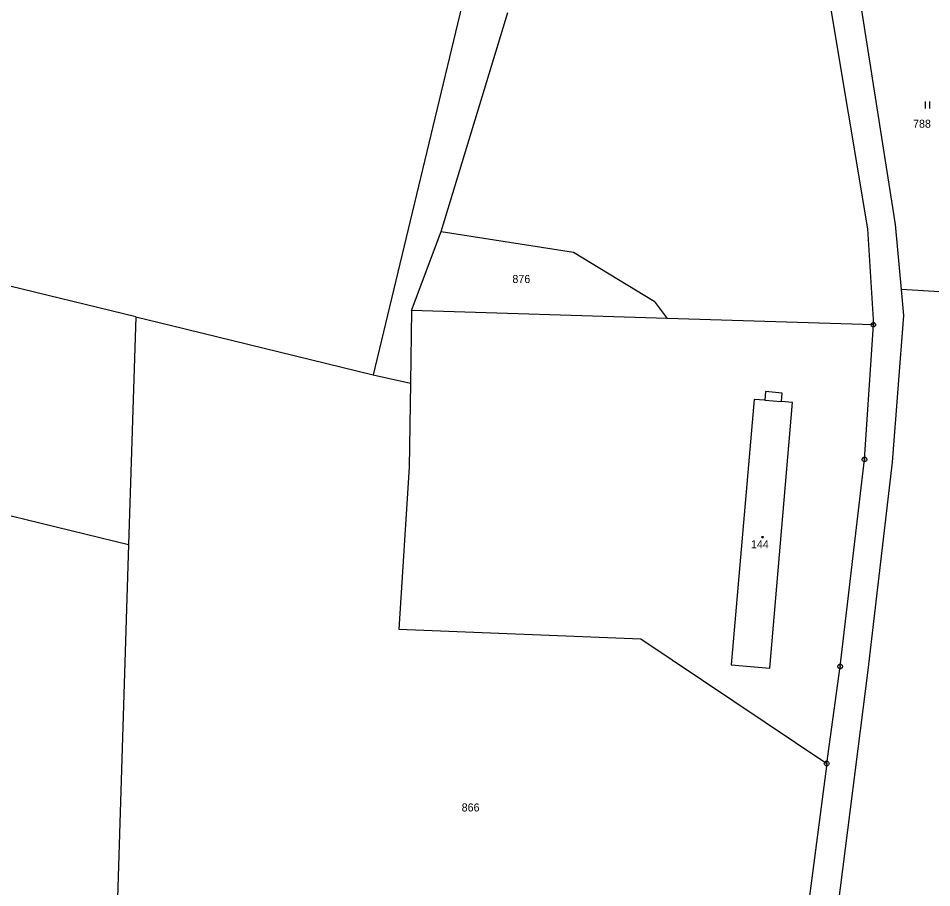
# Model space of a CAD drawing. Extents: x -812394 to -807601, y -1013098 to -1009266.
# Drawn here: x -809612.2 to -809418.3, y -1010586.4 to -1010401.8 of the extents above; entities that cross this region are included whole.
import ezdxf

# ---------------------------------------------------------------- set-up
doc = ezdxf.new("R2010")
doc.units = 0
for name, color, linetype in [('KN_HRANICE', 7, 'Continuous'), ('KN_KULTURY', 7, 'Continuous'), ('KN_MEZNIKY', 7, 'Continuous'), ('KN_PARCELY', 7, 'Continuous'), ('KN_SLUCKY', 7, 'Continuous')]:
    doc.layers.add(name, color=color, linetype=linetype)

# ---------------------------------------------------------------- blocks, each defined once
blk = doc.blocks.new('306')
for p, q in [((-0.5, 1.5), (-0.5, 0)), ((0.5, 0), (0.5, 1.5))]:
    blk.add_line(p, q)
blk = doc.blocks.new('105')
blk.add_line((-0.12, 0), (0.12, 0))
blk.add_lwpolyline([(0.15, 0.48), (0.4, 0.3), (0.5, 0.01), (0.4, -0.28), (0.15, -0.46), (-0.16, -0.46), (-0.41, -0.28), (-0.51, 0.01), (-0.41, 0.3), (-0.16, 0.48), (0.15, 0.48)])
blk = doc.blocks.new('402')
blk.add_lwpolyline([(0.09, 0.15), (0.18, 0), (0.09, -0.15), (-0.09, -0.15), (-0.18, 0), (-0.09, 0.15), (0.09, 0.15)])

msp = doc.modelspace()

# ---------------------------------------------------------------- linework, layer by layer
at = {"layer": 'KN_HRANICE'}
for p, q in [((-809450.65, -1010334.75), (-809431.9, -1010446.55)), ((-809425.97, -1010445.61), (-809436.85, -1010376.65)), ((-809514.24, -1010383.44), (-809536.89, -1010477.53)), ((-809522.42, -1010447.11), (-809508.32, -1010400.6)), ((-809587.27, -1010465.23), (-809714.42, -1010434.16)), ((-809528.75, -1010463.9), (-809522.42, -1010447.11)), ((-809522.42, -1010447.11), (-809494.36, -1010451.5)), ((-809431.9, -1010446.55), (-809430.67, -1010466.91)), ((-809424.72, -1010459.4), (-809425.97, -1010445.61)), ((-809494.36, -1010451.5), (-809477.25, -1010461.87)), ((-809416.64, -1010459.93), (-809424.72, -1010459.4)), ((-809424.21, -1010464.95), (-809424.72, -1010459.4)), ((-809477.25, -1010461.87), (-809474.49, -1010465.57)), ((-809528.75, -1010463.9), (-809528.97, -1010479.27)), ((-809474.49, -1010465.57), (-809528.75, -1010463.9)), ((-809587.27, -1010465.23), (-809588.81, -1010513.56)), ((-809587.27, -1010465.23), (-809580, -1010467)), ((-809430.67, -1010466.91), (-809474.49, -1010465.57)), ((-809426.59, -1010496.04), (-809424.21, -1010464.95)), ((-809580, -1010467), (-809536.89, -1010477.53)), ((-809536.89, -1010477.53), (-809528.97, -1010479.27)), ((-809729.65, -1010479.3), (-809588.81, -1010513.56)), ((-809528.97, -1010479.27), (-809529.22, -1010497.13)), ((-809529.22, -1010497.13), (-809531.43, -1010531.51)), ((-809431.77, -1010540.21), (-809426.59, -1010496.04)), ((-809588.81, -1010513.56), (-809591.38, -1010594.61)), ((-809531.43, -1010531.51), (-809480.06, -1010533.57)), ((-809480.06, -1010533.57), (-809440.59, -1010560.03)), ((-809445.19, -1010645.2), (-809431.77, -1010540.21)), ((-809440.59, -1010560.03), (-809444.6, -1010590.99))]:
    msp.add_line(p, q, dxfattribs=at)
msp.add_lwpolyline([(-809440.59, -1010560.03), (-809437.72, -1010539.45), (-809432.57, -1010495.49), (-809430.67, -1010466.91)], dxfattribs=at)
at = {"layer": 'KN_SLUCKY'}
msp.add_line((-809453.74, -1010482.93), (-809450.22, -1010483.22), dxfattribs=at)
for points in [[(-809450.22, -1010483.22), (-809450.07, -1010481.4), (-809453.59, -1010481.09), (-809453.74, -1010482.93)], [(-809453.74, -1010482.93), (-809456, -1010482.74), (-809460.85, -1010539.12)], [(-809460.85, -1010539.12), (-809452.7, -1010539.8), (-809447.88, -1010483.41), (-809450.22, -1010483.22)]]:
    msp.add_lwpolyline(points, dxfattribs=at)

# ---------------------------------------------------------------- block references
at = {"layer": 'KN_KULTURY'}
for name, p in [('306', (-809419.22, -1010421.03)), ('402', (-809454.22, -1010512))]:
    msp.add_blockref(name, p, dxfattribs=at)
at = {"layer": 'KN_MEZNIKY'}
for p in [(-809430.67, -1010466.91), (-809432.57, -1010495.49), (-809437.72, -1010539.45), (-809440.59, -1010560.03)]:
    msp.add_blockref('105', p, dxfattribs=at)

# ---------------------------------------------------------------- texts
at = {"layer": 'KN_PARCELY'}
for s, p in [('788', (-809422.26, -1010425.08)), ('876', (-809507.32, -1010458.03)), ('144', (-809456.68, -1010514.34)), ('866', (-809518.09, -1010570.21))]:
    msp.add_text(s, height=1.7, dxfattribs=at).set_placement(p)

doc.saveas('drawing.dxf')
